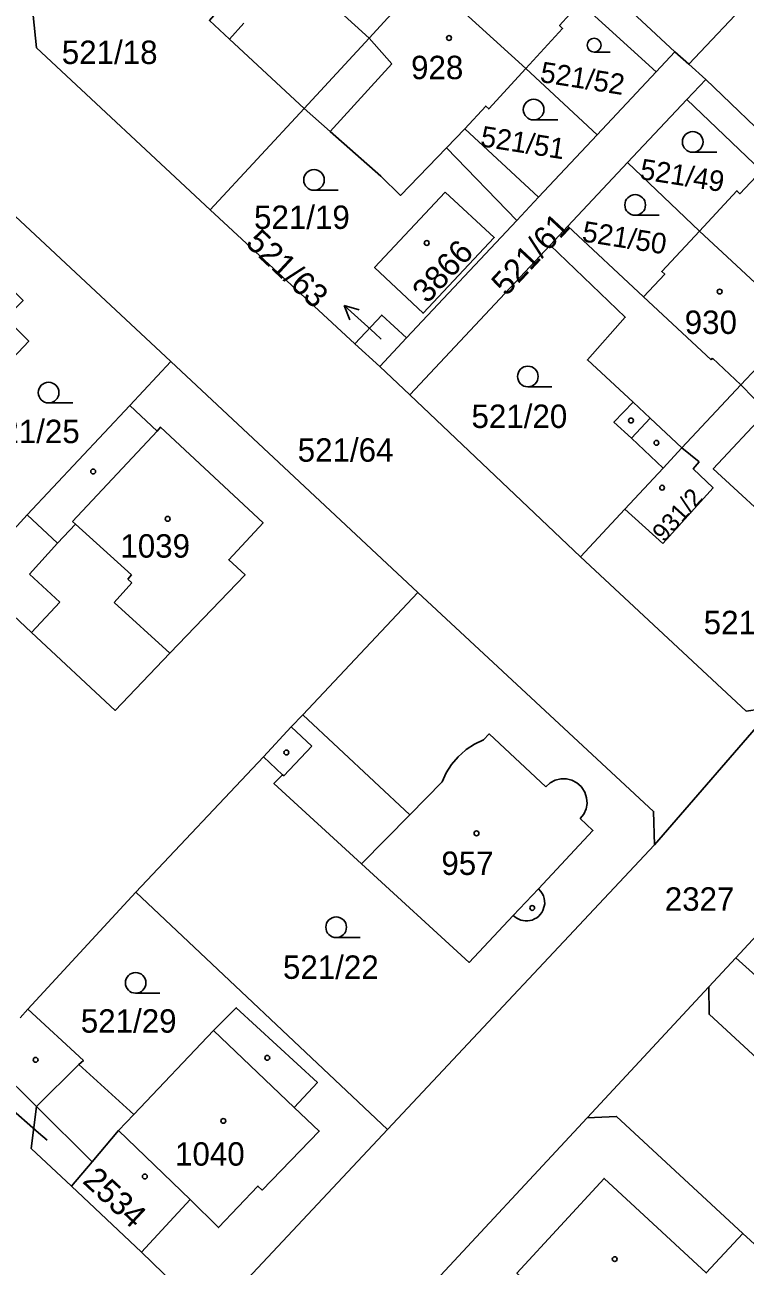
# Model space of a CAD drawing. Extents: x -679220 to -673243, y -1075091 to -1066557.
# Drawn here: x -675907.3 to -675855, y -1071743.1 to -1071652.9 of the extents above; entities that cross this region are included whole.
import ezdxf

# ---------------------------------------------------------------- set-up
doc = ezdxf.new("R2010")
doc.units = 0
for name, color, linetype in [('Hranice parcel', 7, 'Continuous'), ('Parcelní čísla', 7, 'Continuous'), ('Pop  PČ popisy', 7, 'Continuous'), ('Vnitřní kresba', 7, 'Continuous'), ('Značky budov', 7, 'Continuous'), ('Značky kultur', 7, 'Continuous')]:
    doc.layers.add(name, color=color, linetype=linetype)

msp = doc.modelspace()

# ---------------------------------------------------------------- linework, layer by layer
at = {"layer": 'Hranice parcel'}
for p, q in [((-675848.4, -1071644.43), (-675859.1, -1071655.78)), ((-675870.95, -1071656.1), (-675878.24, -1071649.44)), ((-675861.47, -1071656.34), (-675860.11, -1071654.88)), ((-675860.11, -1071654.88), (-675859.1, -1071655.78)), ((-675859.1, -1071655.78), (-675857.88, -1071656.89)), ((-675865.77, -1071660.92), (-675870.95, -1071656.1)), ((-675865.77, -1071660.92), (-675861.47, -1071656.34)), ((-675857.88, -1071656.89), (-675859.25, -1071658.34)), ((-675859.25, -1071658.34), (-675863.55, -1071662.93)), ((-675887.04, -1071658.99), (-675893.87, -1071666.36)), ((-675870.01, -1071665.44), (-675865.77, -1071660.92)), ((-675863.55, -1071662.93), (-675867.88, -1071667.55)), ((-675863.55, -1071662.93), (-675858.34, -1071667.91)), ((-675871.6, -1071667.14), (-675870.01, -1071665.44)), ((-675893.87, -1071666.36), (-675883.35, -1071676.09)), ((-675879.6, -1071675.67), (-675871.6, -1071667.14)), ((-675867.88, -1071667.55), (-675869.17, -1071668.92)), ((-675851.15, -1071674.6), (-675858.34, -1071667.91)), ((-675869.17, -1071668.92), (-675879.37, -1071679.8)), ((-675855.32, -1071679.07), (-675851.15, -1071674.6)), ((-675881.55, -1071677.75), (-675879.6, -1071675.67)), ((-675883.35, -1071676.09), (-675881.55, -1071677.75)), ((-675896.71, -1071677.37), (-675899.7, -1071680.57)), ((-675878.79, -1071694.15), (-675896.71, -1071677.37)), ((-675881.55, -1071677.75), (-675879.37, -1071679.8)), ((-675859.61, -1071683.66), (-675855.32, -1071679.07)), ((-675853.45, -1071681.02), (-675855.32, -1071679.07)), ((-675879.37, -1071679.8), (-675866.98, -1071691.57)), ((-675860.97, -1071685.12), (-675859.61, -1071683.66)), ((-675859.61, -1071683.66), (-675858.35, -1071684.67)), ((-675863.75, -1071688.1), (-675860.97, -1071685.12)), ((-675866.98, -1071691.57), (-675863.75, -1071688.1)), ((-675860.99, -1071690.6), (-675863.75, -1071688.1)), ((-675878.79, -1071694.15), (-675887.14, -1071703.04)), ((-675861.59, -1071712.49), (-675852.95, -1071702.5)), ((-675890, -1071706.09), (-675899.25, -1071715.94)), ((-675880.99, -1071733.17), (-675861.59, -1071712.49)), ((-675849.86, -1071714.41), (-675855.69, -1071720.69)), ((-675907.1, -1071724.43), (-675899.25, -1071715.94)), ((-675899.25, -1071715.94), (-675880.99, -1071733.17)), ((-675855.69, -1071720.69), (-675857.65, -1071722.81)), ((-675857.65, -1071722.81), (-675866.48, -1071732.32)), ((-675907.1, -1071724.43), (-675907.67, -1071725.05)), ((-675910.21, -1071727.8), (-675906.48, -1071731.5)), ((-675906.48, -1071731.5), (-675902.43, -1071735.52)), ((-675866.48, -1071732.32), (-675883.86, -1071750.99)), ((-675893.86, -1071746.89), (-675880.99, -1071733.17)), ((-675902.43, -1071735.52), (-675903.94, -1071737.3)), ((-675903.94, -1071737.3), (-675898.85, -1071742.09)), ((-675898.85, -1071742.09), (-675895.31, -1071738.26)), ((-675847.84, -1071747.53), (-675855.18, -1071740.72)), ((-675898.85, -1071742.09), (-675893.86, -1071746.89))]:
    msp.add_line(p, q, dxfattribs=at)
for points in [[(-675860.11, -1071654.88), (-675865.58, -1071649.78), (-675863.95, -1071647.98), (-675861.72, -1071645.51), (-675863.2, -1071644.17), (-675863.89, -1071644.9), (-675869.35, -1071639.78)], [(-675897.55, -1071642.97), (-675890.75, -1071649.02), (-675892.92, -1071651.46), (-675893.92, -1071652.6), (-675892.45, -1071653.96), (-675887.04, -1071658.99)], [(-675887.04, -1071658.99), (-675882.32, -1071653.9), (-675878.24, -1071649.44)], [(-675870.95, -1071656.1), (-675868.27, -1071653.18), (-675868.49, -1071652.98), (-675866.99, -1071651.33), (-675861.47, -1071656.34)], [(-675906.72, -1071652.25), (-675906.47, -1071654.59), (-675893.87, -1071666.36)], [(-675870.01, -1071665.44), (-675875.36, -1071660.48), (-675873.85, -1071658.83), (-675873.63, -1071659.03), (-675870.95, -1071656.1)], [(-675841.35, -1071664.14), (-675843.75, -1071661.94), (-675844.89, -1071660.89), (-675846.24, -1071662.37), (-675849.75, -1071659.14), (-675852.48, -1071662.07), (-675857.88, -1071656.89)], [(-675859.25, -1071658.34), (-675853.84, -1071663.53), (-675855.39, -1071665.19), (-675855.61, -1071664.98), (-675858.34, -1071667.91)], [(-675871.6, -1071667.14), (-675876.71, -1071661.86), (-675880.05, -1071665.31), (-675881.48, -1071663.91), (-675885.15, -1071660.66), (-675887.04, -1071658.99)], [(-675896.71, -1071677.37), (-675913.5, -1071661.73), (-675915.58, -1071661.71)], [(-675915.25, -1071684.61), (-675907.04, -1071675.9), (-675908.71, -1071674.24), (-675907.45, -1071672.96), (-675911.18, -1071669.27), (-675910.97, -1071669.06), (-675914.88, -1071665.19), (-675918.61, -1071668.97), (-675918.82, -1071668.76), (-675921.95, -1071671.93), (-675921.74, -1071672.14), (-675922.81, -1071673.22), (-675924.8, -1071671.12)], [(-675876.79, -1071665.07), (-675873.24, -1071668.38), (-675878.4, -1071673.87), (-675881.92, -1071670.56), (-675876.79, -1071665.07)], [(-675858.34, -1071667.91), (-675861.07, -1071670.83), (-675860.85, -1071671.04), (-675862.39, -1071672.68), (-675867.88, -1071667.55)], [(-675869.17, -1071668.92), (-675863.72, -1071674.17), (-675866.47, -1071677.26), (-675863.15, -1071680.34), (-675864.54, -1071681.78), (-675863.28, -1071682.96), (-675860.97, -1071685.12)], [(-675883.35, -1071676.09), (-675881.4, -1071674.01), (-675879.6, -1071675.67)], [(-675911.25, -1071692.93), (-675906.83, -1071697.06), (-675900.77, -1071702.73), (-675896.78, -1071698.57), (-675891.33, -1071692.89), (-675892.51, -1071691.78), (-675890.02, -1071689.11), (-675897.46, -1071682.15), (-675897.72, -1071682.43), (-675899.7, -1071680.57)], [(-675899.7, -1071680.57), (-675907.14, -1071688.53), (-675909.14, -1071690.68)], [(-675846.79, -1071684.4), (-675847, -1071684.24), (-675852.24, -1071689.88), (-675857.33, -1071685.18), (-675853.45, -1071681.02)], [(-675858.35, -1071684.67), (-675858.79, -1071685.18), (-675857.35, -1071686.55), (-675860.99, -1071690.6)], [(-675866.98, -1071691.57), (-675854.95, -1071702.78), (-675852.95, -1071702.5)], [(-675861.59, -1071712.49), (-675861.67, -1071710.06), (-675878.79, -1071694.15)], [(-675887.14, -1071703.04), (-675887.97, -1071703.93), (-675890, -1071706.09)], [(-675877.02, -1071707.92), (-675879.37, -1071710.32), (-675887.14, -1071703.04)], [(-675869.48, -1071708.27), (-675873.6, -1071704.44), (-675874.01, -1071704.86)], [(-675874.01, -1071704.86), (-675874.666, -1071705.172), (-675875.273, -1071705.571), (-675875.319, -1071705.606), (-675875.861, -1071706.091), (-675876.33, -1071706.645), (-675876.719, -1071707.259), (-675877.02, -1071707.92)], [(-675890, -1071706.09), (-675888.62, -1071707.4), (-675889.23, -1071708.04), (-675882.87, -1071713.88), (-675875.05, -1071721.04), (-675871.85, -1071717.62), (-675871.73, -1071717.73), (-675871.59, -1071717.83), (-675871.3, -1071717.96), (-675871.14, -1071718), (-675870.99, -1071718.02), (-675870.8, -1071718.02), (-675870.64, -1071718), (-675870.49, -1071717.96), (-675870.3, -1071717.88), (-675870.15, -1071717.79), (-675870, -1071717.67), (-675869.89, -1071717.56), (-675869.78, -1071717.41), (-675869.7, -1071717.26), (-675869.6, -1071716.96), (-675869.57, -1071716.77), (-675869.58, -1071716.57), (-675869.61, -1071716.38), (-675869.67, -1071716.19), (-675869.75, -1071716.03), (-675869.84, -1071715.89), (-675870.03, -1071715.69), (-675866.07, -1071711.46), (-675866.99, -1071710.59)], [(-675866.99, -1071710.59), (-675866.737, -1071710.264), (-675866.569, -1071709.887), (-675866.497, -1071709.481), (-675866.525, -1071709.069), (-675866.651, -1071708.676), (-675866.867, -1071708.325), (-675866.921, -1071708.261), (-675867.23, -1071707.988), (-675867.595, -1071707.796), (-675867.996, -1071707.698), (-675868.409, -1071707.7), (-675868.809, -1071707.8), (-675869.173, -1071707.994), (-675869.48, -1071708.27)], [(-675846.99, -1071717.06), (-675852.76, -1071723.33), (-675855.69, -1071720.69)], [(-675857.65, -1071722.81), (-675857.64, -1071724.8), (-675842.49, -1071738.77)], [(-675895.31, -1071738.26), (-675893.25, -1071740.3), (-675890.39, -1071737.28), (-675890.08, -1071737.57), (-675885.94, -1071733.29), (-675887.76, -1071731.57), (-675886.08, -1071729.76), (-675891.97, -1071724.33), (-675893.63, -1071725.99), (-675899.41, -1071732.08), (-675903.39, -1071728.46), (-675903.07, -1071728.16), (-675907.1, -1071724.43)], [(-675903.94, -1071737.3), (-675906.87, -1071734.55), (-675906.48, -1071731.5)], [(-675855.18, -1071740.72), (-675864.35, -1071732.22), (-675866.48, -1071732.32)], [(-675902.43, -1071735.52), (-675900.51, -1071733.24), (-675895.31, -1071738.26)], [(-675855.18, -1071740.72), (-675857.84, -1071743.59), (-675865.26, -1071736.73), (-675871.59, -1071743.6), (-675863.02, -1071751.44), (-675865.29, -1071753.91), (-675859.18, -1071759.65)]]:
    msp.add_lwpolyline(points, dxfattribs=at)
at = {"layer": 'Pop  PČ popisy'}
for p, q in [((-675881.9, -1071675.33), (-675884.13, -1071673.322)), ((-675884.13, -1071673.322), (-675883.051, -1071673.62)), ((-675884.13, -1071673.322), (-675883.721, -1071674.364)), ((-675881.44, -1071675.75), (-675881.9, -1071675.33)), ((-675906.32, -1071733.41), (-675908.585, -1071731.441)), ((-675905.71, -1071733.94), (-675906.32, -1071733.41))]:
    msp.add_line(p, q, dxfattribs=at)
at = {"layer": 'Vnitřní kresba'}
for p, q in [((-675884.39, -1071652.01), (-675882.32, -1071653.9)), ((-675891.42, -1071652.79), (-675892.45, -1071653.96)), ((-675882.32, -1071653.9), (-675880.67, -1071655.76)), ((-675880.67, -1071655.76), (-675885.15, -1071660.66)), ((-675876.71, -1071661.86), (-675875.36, -1071660.48)), ((-675857.49, -1071677.25), (-675862.39, -1071672.68)), ((-675857.38, -1071677.14), (-675857.49, -1071677.25)), ((-675855.32, -1071679.07), (-675857.38, -1071677.14)), ((-675863.15, -1071680.34), (-675861.91, -1071681.5)), ((-675861.91, -1071681.5), (-675863.28, -1071682.96)), ((-675861.91, -1071681.5), (-675859.61, -1071683.66)), ((-675903.85, -1071689), (-675897.72, -1071682.43)), ((-675904.95, -1071690.58), (-675907.14, -1071688.53)), ((-675904.95, -1071690.58), (-675903.65, -1071689.19)), ((-675903.65, -1071689.19), (-675903.85, -1071689)), ((-675899.57, -1071692.89), (-675903.65, -1071689.19)), ((-675906.97, -1071692.82), (-675904.95, -1071690.58)), ((-675904.78, -1071694.87), (-675906.97, -1071692.82)), ((-675900.84, -1071694.88), (-675899.54, -1071693.46)), ((-675899.84, -1071693.19), (-675899.57, -1071692.89)), ((-675899.54, -1071693.46), (-675899.84, -1071693.19)), ((-675906.83, -1071697.06), (-675904.78, -1071694.87)), ((-675896.78, -1071698.57), (-675900.84, -1071694.88)), ((-675887.97, -1071703.93), (-675886.49, -1071705.32)), ((-675886.49, -1071705.32), (-675888.52, -1071707.48)), ((-675888.52, -1071707.48), (-675888.62, -1071707.4)), ((-675879.37, -1071710.32), (-675882.87, -1071713.88)), ((-675870.03, -1071715.69), (-675871.85, -1071717.62)), ((-675893.63, -1071725.99), (-675887.76, -1071731.57)), ((-675903.39, -1071728.46), (-675906.48, -1071731.5)), ((-675900.51, -1071733.24), (-675899.41, -1071732.08))]:
    msp.add_line(p, q, dxfattribs=at)
at = {"layer": 'Značky budov'}
for centre in [(-675876.517, -1071653.879), (-675878.137, -1071668.769), (-675856.867, -1071672.299), (-675863.307, -1071681.669), (-675861.457, -1071683.289), (-675902.357, -1071685.369), (-675861.047, -1071686.549), (-675896.947, -1071688.809), (-675888.327, -1071705.789), (-675874.527, -1071711.659), (-675870.477, -1071717.079), (-675906.537, -1071728.109), (-675889.717, -1071727.969), (-675892.907, -1071732.549), (-675898.607, -1071736.589), (-675864.487, -1071742.589)]:
    msp.add_circle(centre, 0.175, dxfattribs=at)
at = {"layer": 'Značky kultur'}
for p, q in [((-675865.985, -1071654.9), (-675864.813, -1071654.9)), ((-675870.373, -1071659.83), (-675868.623, -1071659.83)), ((-675858.823, -1071662.18), (-675857.073, -1071662.18)), ((-675886.323, -1071664.94), (-675884.573, -1071664.94)), ((-675863.003, -1071666.76), (-675861.253, -1071666.76)), ((-675870.793, -1071679.22), (-675869.043, -1071679.22)), ((-675905.593, -1071680.39), (-675903.843, -1071680.39)), ((-675884.713, -1071719.23), (-675882.963, -1071719.23)), ((-675899.273, -1071723.27), (-675897.523, -1071723.27))]:
    msp.add_line(p, q, dxfattribs=at)
for centre, radius in [((-675865.985, -1071654.397), 0.502), ((-675870.373, -1071659.08), 0.75), ((-675858.823, -1071661.43), 0.75), ((-675886.323, -1071664.19), 0.75), ((-675863.003, -1071666.01), 0.75), ((-675870.793, -1071678.47), 0.75), ((-675905.593, -1071679.64), 0.75), ((-675884.713, -1071718.48), 0.75), ((-675899.273, -1071722.52), 0.75)]:
    msp.add_circle(centre, radius, dxfattribs=at)

# ---------------------------------------------------------------- texts
at = {"layer": 'Parcelní čísla'}
for s, p in [('521/18', (-675904.637, -1071655.769)), ('928', (-675879.275, -1071656.87)), ('521/19', (-675890.677, -1071667.749)), ('930', (-675859.405, -1071675.38)), ('521/20', (-675874.887, -1071682.21)), ('521/25', (-675910.287, -1071683.31)), ('521/64', (-675887.507, -1071684.66)), ('1039', (-675900.384, -1071691.63)), ('521/21', (-675858.027, -1071697.19)), ('957', (-675877.075, -1071714.68)), ('2327', (-675860.854, -1071717.279)), ('521/22', (-675888.577, -1071722.229)), ('521/29', (-675903.257, -1071726.14)), ('1040', (-675896.414, -1071735.8))]:
    msp.add_text(s, height=1.7, dxfattribs=at).set_placement(p)
for s, height, rotation, p in [('521/52', 1.5, 351, (-675869.967, -1071657.065)), ('521/51', 1.5, 351, (-675874.297, -1071661.735)), ('521/49', 1.5, 351, (-675862.727, -1071664.115)), ('521/61', 1.7, 47, (-675872.36, -1071672.696)), ('521/50', 1.5, 351, (-675866.917, -1071668.645)), ('521/63', 1.7, 317, (-675891.373, -1071668.867)), ('3866', 1.7, 47, (-675878.096, -1071673.234)), ('931/2', 1.3, 48, (-675860.914, -1071690.569)), ('2534', 1.7, 317, (-675903.204, -1071736.993))]:
    msp.add_text(s, height=height, rotation=rotation, dxfattribs=at).set_placement(p)

doc.saveas('drawing.dxf')
